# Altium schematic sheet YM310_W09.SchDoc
size 431 x 279 mm
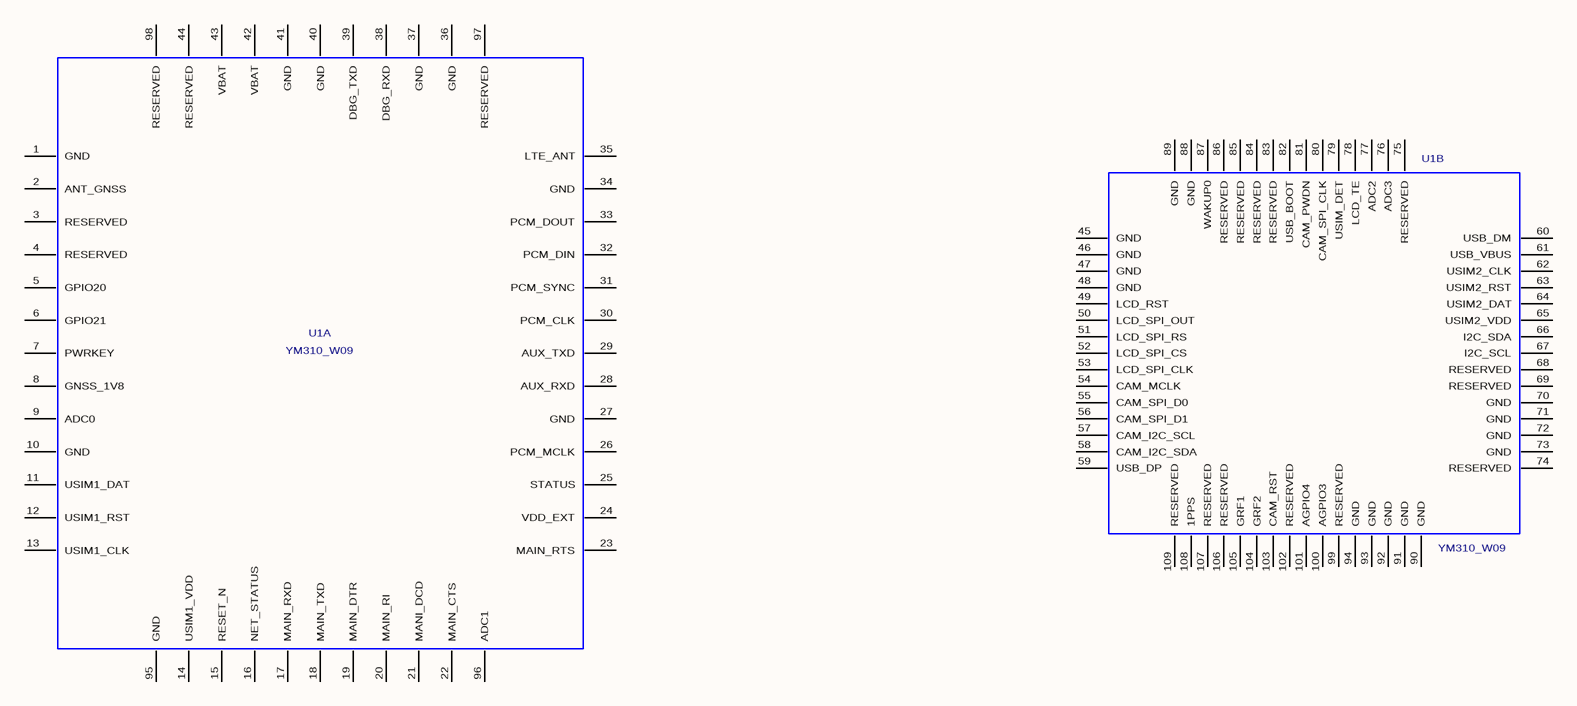
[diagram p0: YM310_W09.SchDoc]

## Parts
U1  YM310_W09  [AIR800E]  (parts A,B of 2)

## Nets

Not connected (* = marked no-connect by the designer): U1 1(GND) 2(ANT_GNSS) 3(RESERVED) 4(RESERVED) 5(GPIO20) 6(GPIO21) 7(PWRKEY) 8(GNSS_1V8) 9(ADC0) 10(GND) 11(USIM1_DAT) 12(USIM1_RST) 13(USIM1_CLK) 14(USIM1_VDD) 15(RESET_N) 16(NET_STATUS) 17(MAIN_RXD) 18(MAIN_TXD) 19(MAIN_DTR) 20(MAIN_RI) 21(MANI_DCD) 22(MAIN_CTS) 23(MAIN_RTS) 24(VDD_EXT) 25(STATUS) 26(PCM_MCLK) 27(GND) 28(AUX_RXD) 29(AUX_TXD) 30(PCM_CLK) 31(PCM_SYNC) 32(PCM_DIN) 33(PCM_DOUT) 34(GND) 35(LTE_ANT) 36(GND) 37(GND) 38(DBG_RXD) 39(DBG_TXD) 40(GND) 41(GND) 42(VBAT) 43(VBAT) 44(RESERVED) 45(GND) 46(GND) 47(GND) 48(GND) 49(LCD_RST) 50(LCD_SPI_OUT) 51(LCD_SPI_RS) 52(LCD_SPI_CS) 53(LCD_SPI_CLK) 54(CAM_MCLK) 55(CAM_SPI_D0) 56(CAM_SPI_D1) 57(CAM_I2C_SCL) 58(CAM_I2C_SDA) 59(USB_DP) 60(USB_DM) 61(USB_VBUS) 62(USIM2_CLK) 63(USIM2_RST) 64(USIM2_DAT) 65(USIM2_VDD) 66(I2C_SDA) 67(I2C_SCL) 68(RESERVED) 69(RESERVED) 70(GND) 71(GND) 72(GND) 73(GND) 74(RESERVED) 75(RESERVED) 76(ADC3) 77(ADC2) 78(LCD_TE) 79(USIM_DET) 80(CAM_SPI_CLK) 81(CAM_PWDN) 82(USB_BOOT) 83(RESERVED) 84(RESERVED) 85(RESERVED) 86(RESERVED) 87(WAKUP0) 88(GND) 89(GND) 90(GND) 91(GND) 92(GND) 93(GND) 94(GND) 95(GND) 96(ADC1) 97(RESERVED) 98(RESERVED) 99(RESERVED) 100(AGPIO3) 101(AGPIO4) 102(RESERVED) 103(CAM_RST) 104(GRF2) 105(GRF1) 106(RESERVED) 107(RESERVED) 108(1PPS) 109(RESERVED)

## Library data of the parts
U1 = YM310_W09: Geometry.Height: 2.4mm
